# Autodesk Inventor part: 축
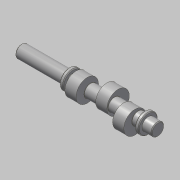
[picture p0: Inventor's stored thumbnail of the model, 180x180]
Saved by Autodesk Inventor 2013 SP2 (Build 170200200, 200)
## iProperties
Company: 한국ATC센터
Created: 2014-08
Part Number: 축
Document SubType Name: Modeling
Designer: mdu
Density: 7.86 g/cm^3
Material: 강철, 연강
Mass: 516.584 g
Surface Area: 162.516 cm^2
Volume: 65.7231 cm^3
Author: mdu
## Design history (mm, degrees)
sketch "스케치1"
  geometry: L1 (-91.5, 0)-(91.5, 0); L2 (-91.5, 0)-(-91.5, 8.5); L3 (-91.5, 8.5)-(-27.5, 8.5); L4 (-27.5, 8.5)-(-27.5, 13); L5 (-27.5, 13)-(-22.5, 13); L6 (-22.5, 13)-(-22.5, 8.5); L7 (-22.5, 8.5)-(73.5, 8.5); L8 (73.5, 8.5)-(73.5, 13); L9 (73.5, 13)-(78.5, 13); L10 (78.5, 13)-(78.5, 8.5); L11 (78.5, 8.5)-(91.5, 8.5); L12 (91.5, 8.5)-(91.5, 0); 2 further points
  constraints: 24 end point, 5 parallel, 1 coincident, 1 horizontal, 1 midpoint, 1 perpendicular
  dimensions: "d0" = 183 distance of L1.start L1.end (derived); "d2" = 17 diameter of L3 L1; "d3" = 26 diameter of L5 L1; "d4" = 17 diameter of L7 L1; "d5" = 26 diameter of L9 L1; "d6" = 17 diameter of L11 L1; "d7" = 5 distance of L8.end L9.end; "d8" = 5 distance of L4.end L5.end; "d10" = 64 distance of L2.end L3.end; "d11" = 13 distance of L10.end L11.end; "d35" = 96 distance between parallel lines of L8 L6
revolve "회전1" sketch "스케치1" stored, may be unused: angle "d12" = 90 deg
node "작업 평면7"
sketch "스케치6"
  geometry: C1 r 15 at (0, 5); 1 further point
  constraints: 1 centre point, 1 vertical alignment
  dimensions: "d37" = 30 diameter of C1; "d38" = 5 distance of C1.centre point (0, 0)
extrude "돌출4" join sketch "스케치6" stored distance "d33" = 15; taper "d34" = 0 deg
node "작업 평면8"
sketch "스케치7"
  geometry: L1 (0, 0)-(-6.5, -11.258); L2 (0, 0)-(13, 0); C1 r 15 at (-2.5, -4.33); A1 r 13 centre (0, 0) between (-6.5, -11.258) and (13, 0) reference; 1 further point
  constraints: 4 end point, 2 point on circle, 1 centre point, 1 horizontal, 1 point on line
  dimensions: "d40" = 120 deg angle of L1 L2; "d41" = 30 diameter of C1; "d42" = 5 distance of point (0, 0) C1.centre
extrude "돌출5" join sketch "스케치7" stored distance "d43" = 15; taper "d44" = 0 deg
node "작업 평면9"
sketch "스케치8"
  geometry: L1 (0, 0)-(4.25, -7.361); L2 (0, 0)-(-8.5, 0); C1 r 15 at (2.5, -4.33); A1 r 8.5 centre (0, 0) between (4.25, -7.361) and (-8.5, 0) reference; 1 further point
  constraints: 4 end point, 2 point on circle, 1 centre point, 1 horizontal, 1 point on line
  dimensions: "d46" = 120 deg angle of L1 L2; "d47" = 30 diameter of C1; "d48" = 5 distance of point (0, 0) C1.centre
extrude "돌출6" join sketch "스케치8" stored distance "d49" = 15; taper "d50" = 0 deg
node "작업 평면3"
sketch "스케치5"
  geometry: L1 (32, 8.5)-(32, -8.5) reference; L2 (27.5, -2.5)-(14.5, -2.5); L3 (14.5, 2.5)-(27.5, 2.5); A1 r 2.5 centre (14.5, 0) between (14.5, 2.5) and (14.5, -2.5); A2 r 2.5 centre (27.5, 0) between (27.5, -2.5) and (27.5, 2.5); 4 further points
  constraints: 4 end point, 4 point on circle, 4 tangent, 2 centre point, 2 point on line, 1 horizontal alignment, 1 midpoint, 1 parallel, 1 perpendicular
  dimensions: "d23" = 5 distance between parallel lines of L3 L2; "d36" = 20 dimension on A1 L1; "d52" = 2 distance edge to line of A2 L1
extrude "돌출3" cut sketch "스케치5" distance "d25" = 3; taper "d26" = 0 deg
chamfer "모따기1" distance "d27" = 1; stored, may be unused: second distance "d28" = 2, angle "d29" = 45 deg
fillet "모깎기1" dims "d51" = 0.3
chamfer "모따기2" distance "d53" = 1; stored, may be unused: second distance "d54" = 2, angle "d55" = 45 deg
node "작업 평면10"
node "솔리드1"
other parameters: "d39" = -32, "d45" = 32
